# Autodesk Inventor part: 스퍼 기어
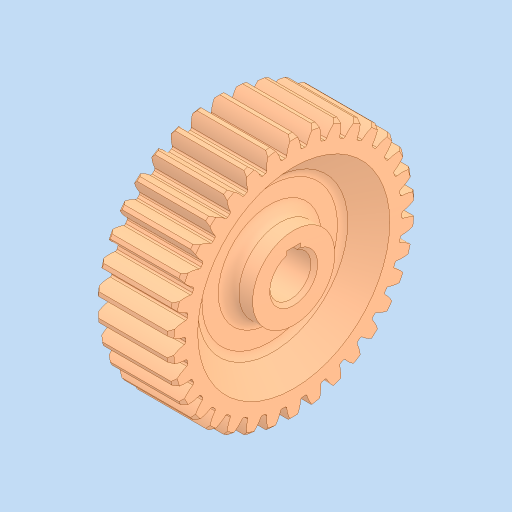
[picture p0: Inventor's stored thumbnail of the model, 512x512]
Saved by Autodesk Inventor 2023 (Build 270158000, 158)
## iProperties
Created: 2026-03
Part Number: 스퍼 기어
Material: 강철, 합금
Document SubType Name: Modeling
Designer: home
Density: 7.73 g/cm^3
Appearance: 기본값
Author: jhkim
Sending System: Autodesk Inventor 2026
Preprocessor: ST-DEVELOPER v20.1
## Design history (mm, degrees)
feature "솔리드1"
node "솔리드2"
